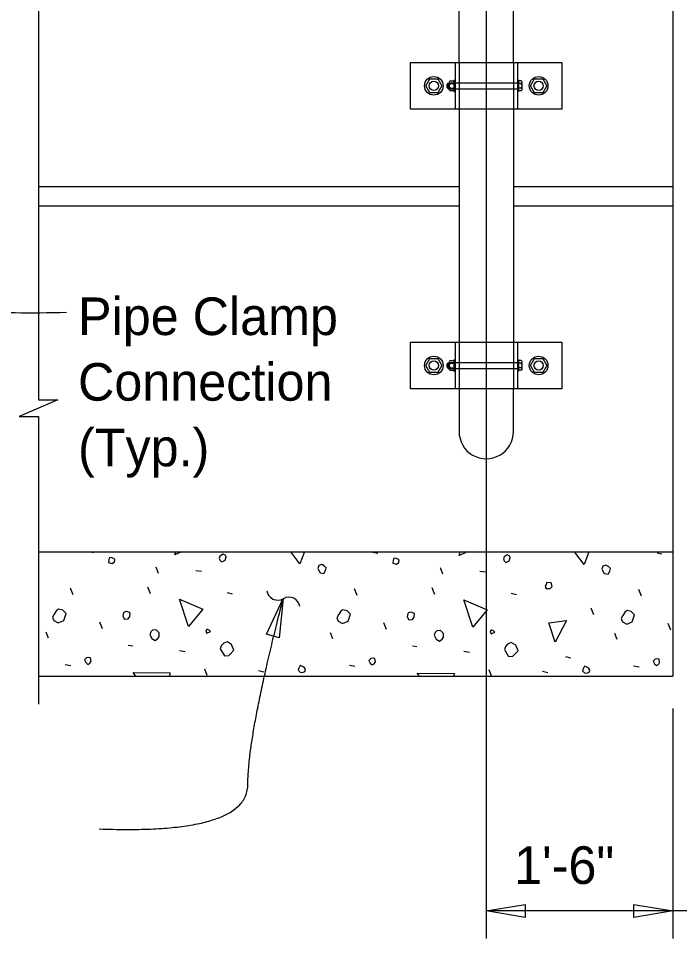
# Model space of a CAD drawing. Extents: x 0 to 41.2, y 0 to 26.
# Drawn here: x 23.735 to 27.279, y 12.395 to 17.331 of the extents above; entities that cross this region are included whole.
import ezdxf

# ---------------------------------------------------------------- set-up
doc = ezdxf.new("R2010")
doc.units = 0
for name, color, linetype in [('CL_Major', 7, 'Continuous'), ('Dimension', 7, 'Continuous'), ('Miscellaneous', 7, 'Continuous'), ('SteelMisc', 7, 'Continuous'), ('SteelMisc_h', 7, 'Continuous'), ('SupstrConc', 7, 'Continuous'), ('TextStructures', 7, 'Continuous')]:
    doc.layers.add(name, color=color, linetype=linetype)

msp = doc.modelspace()

# ---------------------------------------------------------------- linework, layer by layer
at = {"layer": 'CL_Major'}
msp.add_line((26.2429, 25.6784), (26.2429, 12.3953), dxfattribs=at)
at = {"layer": 'Dimension'}
for p, q in [((27.2429, 13.6294), (27.2429, 12.3953)), ((28.5763, 12.5434), (26.2429, 12.5434))]:
    msp.add_line(p, q, dxfattribs=at)
for points in [[(23.8431, 20.1983), (23.8431, 19.1806), (23.9465, 19.1806), (23.8431, 19.1356), (23.7398, 19.0906), (23.8431, 19.0906), (23.8431, 17.1361)], [(23.8431, 17.1361), (23.8431, 15.2855), (23.9464, 15.2855), (23.8431, 15.2405), (23.7397, 15.1955), (23.8431, 15.1955), (23.8431, 13.653)]]:
    msp.add_lwpolyline(points, dxfattribs=at)
for points in [[(25.1546, 14.219), (25.1324, 14.009), (25.0644, 14.0281)], [(26.2429, 12.5434), (26.4512, 12.5787), (26.4512, 12.5081)], [(27.2429, 12.5434), (27.0347, 12.5081), (27.0347, 12.5787)]]:
    msp.add_lwpolyline(points, close=True, dxfattribs=at)
for centre, start, end in [((25.1255, 14.2702), 188.4294, 300.1567), ((25.1854, 14.1671), 8.4294, 120.1567)]:
    msp.add_arc(centre, 0.0596, start, end, dxfattribs=at)
for points in [[(23.9932, 15.7529), (23.0399, 15.7236), (23.3618, 16.2556), (23.3935, 16.8155), (23.1813, 16.9916), (22.6122, 16.9694)], [(24.1685, 12.9835), (24.964, 12.9538), (24.9656, 13.4901), (25.1547, 14.2189)]]:
    msp.add_open_spline(points, degree=2, dxfattribs=at)
at = {"layer": 'Miscellaneous'}
for p, q in [((26.0354, 16.9625), (26.0354, 16.9746)), ((26.0411, 16.9625), (26.0411, 16.9746)), ((26.0354, 15.4625), (26.0354, 15.4746)), ((26.0411, 15.4625), (26.0411, 15.4746)), ((24.1186, 14.4695), (24.1373, 14.4657)), ((25.6346, 14.4675), (25.6611, 14.4622)), ((27.1584, 14.4639), (27.185, 14.4586)), ((24.4856, 14.3543), (24.4732, 14.3879)), ((24.6853, 14.3702), (24.7172, 14.3667)), ((26.0094, 14.3508), (25.997, 14.3844)), ((26.2092, 14.3667), (26.241, 14.3632)), ((24.0277, 14.2394), (24.0136, 14.2748)), ((24.4432, 14.2447), (24.429, 14.2801)), ((25.5515, 14.2359), (25.5374, 14.2712)), ((25.967, 14.2412), (25.9528, 14.2765)), ((27.0754, 14.2324), (27.0612, 14.2677)), ((24.8533, 14.2518), (24.8816, 14.2447)), ((26.3771, 14.2483), (26.4054, 14.2412)), ((26.819, 14.1316), (26.8049, 14.1669)), ((24.1851, 14.0573), (24.1709, 14.0927)), ((25.7089, 14.0538), (25.6947, 14.0892)), ((27.2327, 14.0503), (27.2185, 14.0856)), ((23.8969, 14.0061), (23.8845, 14.0397)), ((25.4207, 14.0025), (25.4084, 14.0361)), ((26.9445, 13.999), (26.9322, 14.0326)), ((24.3229, 13.969), (24.3477, 13.9654)), ((24.5987, 13.9407), (24.6288, 13.9354)), ((25.8468, 13.9654), (25.8715, 13.9619)), ((26.1225, 13.9371), (26.1526, 13.9318)), ((26.667, 13.9089), (26.6953, 13.9018)), ((23.9853, 13.8647), (24.0154, 13.8594)), ((24.7472, 13.8063), (24.7348, 13.8399)), ((25.0212, 13.8328), (25.0495, 13.8258)), ((25.5091, 13.8611), (25.5392, 13.8558)), ((26.271, 13.8028), (26.2587, 13.8364)), ((26.545, 13.8293), (26.5733, 13.8222)), ((27.0329, 13.8576), (27.063, 13.8523))]:
    msp.add_line(p, q, dxfattribs=at)
for points in [[(24.574, 14.4533), (24.5789, 14.4695)], [(24.6099, 14.4695), (24.574, 14.4533)], [(25.244, 14.4056), (25.1954, 14.4695)], [(25.2678, 14.4695), (25.244, 14.4056)], [(26.0978, 14.4498), (26.1038, 14.4695)], [(26.1416, 14.4695), (26.0978, 14.4498)], [(26.7678, 14.4021), (26.7165, 14.4695)], [(26.793, 14.4695), (26.7678, 14.4021)], [(24.2186, 14.4127), (24.2381, 14.4074), (24.2505, 14.4162), (24.2522, 14.4286), (24.2487, 14.4321), (24.2346, 14.4392), (24.2222, 14.4374), (24.2204, 14.425), (24.2186, 14.4127)], [(24.8215, 14.418), (24.8285, 14.418), (24.8427, 14.425), (24.848, 14.4409), (24.8462, 14.4498), (24.8321, 14.4569), (24.8144, 14.4463), (24.8109, 14.4356), (24.8144, 14.425), (24.8215, 14.418)], [(25.7425, 14.4091), (25.7619, 14.4038), (25.7743, 14.4127), (25.7761, 14.425), (25.7725, 14.4286), (25.7584, 14.4356), (25.746, 14.4339), (25.7442, 14.4215), (25.7425, 14.4091)], [(26.3453, 14.4144), (26.3523, 14.4144), (26.3665, 14.4215), (26.3718, 14.4374), (26.37, 14.4463), (26.3559, 14.4533), (26.3382, 14.4427), (26.3347, 14.4321), (26.3382, 14.4215), (26.3453, 14.4144)], [(25.3429, 14.3738), (25.3518, 14.3579), (25.373, 14.3543), (25.3818, 14.3702), (25.3854, 14.3844), (25.3765, 14.3932), (25.3606, 14.4021), (25.3447, 14.3968), (25.3394, 14.3808), (25.3429, 14.3738)], [(26.8668, 14.3702), (26.8756, 14.3543), (26.8968, 14.3508), (26.9057, 14.3667), (26.9092, 14.3808), (26.9004, 14.3897), (26.8844, 14.3985), (26.8685, 14.3932), (26.8632, 14.3773), (26.8668, 14.3702)], [(26.5645, 14.273), (26.5857, 14.273), (26.5963, 14.2836), (26.591, 14.3031), (26.568, 14.3048), (26.5645, 14.2942), (26.5592, 14.2854), (26.5645, 14.273), (26.5609, 14.2765)], [(24.6464, 14.0697), (24.5987, 14.2164), (24.7242, 14.1616), (24.6464, 14.0697)], [(26.1703, 14.0662), (26.1225, 14.2129), (26.248, 14.1581), (26.1703, 14.0662)], [(23.9252, 14.1015), (23.9482, 14.0892), (23.9782, 14.1015), (23.9906, 14.1387), (23.9729, 14.1563), (23.9499, 14.1616), (23.9393, 14.1546), (23.927, 14.1351), (23.9181, 14.1192), (23.9252, 14.1015)], [(24.2947, 14.1245), (24.3035, 14.1086), (24.3229, 14.1104), (24.3318, 14.1228), (24.3336, 14.1422), (24.3212, 14.1475), (24.3123, 14.1493), (24.3017, 14.1457), (24.2982, 14.1422), (24.2947, 14.1245)], [(25.449, 14.098), (25.472, 14.0856), (25.502, 14.098), (25.5144, 14.1351), (25.4967, 14.1528), (25.4738, 14.1581), (25.4632, 14.151), (25.4508, 14.1316), (25.4419, 14.1157), (25.449, 14.098)], [(25.8185, 14.121), (25.8273, 14.1051), (25.8468, 14.1068), (25.8556, 14.1192), (25.8574, 14.1387), (25.845, 14.144), (25.8362, 14.1457), (25.8255, 14.1422), (25.822, 14.1387), (25.8185, 14.121)], [(26.9728, 14.0945), (26.9958, 14.0821), (27.0259, 14.0945), (27.0382, 14.1316), (27.0206, 14.1493), (26.9976, 14.1546), (26.987, 14.1475), (26.9746, 14.1281), (26.9658, 14.1121), (26.9728, 14.0945)], [(26.6122, 13.9849), (26.5786, 14.0892), (26.6723, 14.1015), (26.6122, 13.9849)], [(24.4396, 14.0255), (24.4502, 14.0043), (24.4679, 13.9937), (24.482, 14.0043), (24.4891, 14.0149), (24.4891, 14.0361), (24.4732, 14.052), (24.4538, 14.0503), (24.4449, 14.0414), (24.4396, 14.0255)], [(24.7454, 14.0344), (24.7649, 14.0432), (24.7578, 14.0503), (24.7454, 14.0556), (24.7401, 14.0432), (24.7454, 14.0344)], [(25.9634, 14.022), (25.974, 14.0008), (25.9917, 13.9902), (26.0059, 14.0008), (26.0129, 14.0114), (26.0129, 14.0326), (25.997, 14.0485), (25.9776, 14.0467), (25.9687, 14.0379), (25.9634, 14.022)], [(26.2693, 14.0308), (26.2887, 14.0397), (26.2816, 14.0467), (26.2693, 14.052), (26.264, 14.0397), (26.2693, 14.0308)], [(24.8162, 13.9495), (24.8391, 13.9124), (24.8621, 13.9142), (24.871, 13.923), (24.8904, 13.9424), (24.878, 13.9725), (24.8533, 13.9866), (24.8356, 13.9796), (24.8215, 13.9654), (24.8162, 13.9495)], [(26.34, 13.946), (26.3629, 13.9089), (26.3859, 13.9106), (26.3948, 13.9195), (26.4142, 13.9389), (26.4018, 13.969), (26.3771, 13.9831), (26.3594, 13.976), (26.3453, 13.9619), (26.34, 13.946)], [(24.0967, 13.877), (24.1073, 13.8664), (24.1179, 13.8735), (24.125, 13.8841), (24.1214, 13.9018), (24.1126, 13.9035), (24.1002, 13.9018), (24.0896, 13.8912), (24.0967, 13.877)], [(25.6205, 13.8735), (25.6311, 13.8629), (25.6417, 13.87), (25.6488, 13.8806), (25.6452, 13.8982), (25.6364, 13.9), (25.624, 13.8982), (25.6134, 13.8876), (25.6205, 13.8735)], [(27.1443, 13.87), (27.1549, 13.8594), (27.1655, 13.8664), (27.1726, 13.877), (27.1691, 13.8947), (27.1602, 13.8965), (27.1478, 13.8947), (27.1372, 13.8841), (27.1443, 13.87)], [(24.3642, 13.8028), (24.3495, 13.8222), (24.5492, 13.8205), (24.5426, 13.8028)], [(25.2457, 13.824), (25.2581, 13.8222), (25.2705, 13.8275), (25.274, 13.8381), (25.2687, 13.847), (25.2581, 13.8541), (25.2457, 13.8594), (25.2386, 13.8452), (25.2351, 13.8346), (25.2457, 13.824)], [(26.7695, 13.8205), (26.7819, 13.8187), (26.7943, 13.824), (26.7978, 13.8346), (26.7925, 13.8434), (26.7819, 13.8505), (26.7695, 13.8558), (26.7625, 13.8417), (26.7589, 13.8311), (26.7695, 13.8205)], [(25.8854, 13.8028), (25.8733, 13.8187), (26.073, 13.8169), (26.0678, 13.8028)]]:
    msp.add_lwpolyline(points, dxfattribs=at)
at = {"layer": 'SteelMisc'}
for p, q in [((26.0971, 17.0944), (26.0971, 17.6079)), ((26.3888, 17.0944), (26.3888, 17.6079)), ((25.837, 17.0944), (26.6489, 17.0944)), ((25.837, 16.8444), (25.837, 17.0944)), ((26.0763, 17.0944), (26.0763, 16.8444)), ((26.4096, 17.0944), (26.4096, 16.8444)), ((26.6489, 17.0944), (26.6489, 16.8444)), ((26.0326, 16.9774), (26.0382, 16.984)), ((26.0382, 16.984), (26.0447, 16.984)), ((26.0382, 16.9541), (26.0382, 16.984)), ((26.0447, 16.9873), (26.0447, 16.9516)), ((26.0494, 16.9824), (26.0697, 16.9824)), ((26.0496, 16.9954), (26.0697, 16.9954)), ((26.0697, 16.9997), (26.0697, 16.9391)), ((26.0697, 16.9997), (26.0763, 16.9997)), ((26.0697, 16.9954), (26.0697, 16.9435)), ((26.4159, 16.9997), (26.4098, 16.9997)), ((26.4159, 16.9997), (26.4159, 16.9391)), ((26.4306, 16.9954), (26.4159, 16.9954)), ((26.4307, 16.9824), (26.4159, 16.9824)), ((26.4357, 16.95), (26.4357, 16.9889)), ((26.0326, 16.9597), (26.0326, 16.9774)), ((26.0326, 16.9597), (26.0382, 16.9541)), ((26.0382, 16.9541), (26.0447, 16.9541)), ((26.0494, 16.9565), (26.0697, 16.9565)), ((26.0497, 16.9435), (26.0697, 16.9435)), ((26.0697, 16.9391), (26.0763, 16.9391)), ((26.4159, 16.9391), (26.4098, 16.9391)), ((26.4307, 16.9564), (26.4159, 16.9564)), ((26.4306, 16.9434), (26.4159, 16.9434)), ((26.6489, 16.8444), (25.837, 16.8444)), ((26.0971, 16.8444), (26.0971, 15.5944)), ((26.3888, 16.8444), (26.3888, 15.5944)), ((25.837, 15.5944), (26.6489, 15.5944)), ((25.837, 15.3444), (25.837, 15.5944)), ((26.0763, 15.5944), (26.0763, 15.3444)), ((26.4096, 15.5944), (26.4096, 15.3444)), ((26.6489, 15.5944), (26.6489, 15.3444)), ((26.0697, 15.4997), (26.0697, 15.4391)), ((26.0697, 15.4997), (26.0763, 15.4997)), ((26.4159, 15.4997), (26.4098, 15.4997)), ((26.4159, 15.4997), (26.4159, 15.4391)), ((26.0326, 15.4774), (26.0382, 15.484)), ((26.0326, 15.4597), (26.0326, 15.4774)), ((26.0326, 15.4597), (26.0382, 15.4541)), ((26.0382, 15.484), (26.0447, 15.484)), ((26.0382, 15.4541), (26.0382, 15.484)), ((26.0382, 15.4541), (26.0447, 15.4541)), ((26.0447, 15.4873), (26.0447, 15.4516)), ((26.0494, 15.4824), (26.0697, 15.4824)), ((26.0494, 15.4565), (26.0697, 15.4565)), ((26.0496, 15.4954), (26.0697, 15.4954)), ((26.0697, 15.4954), (26.0697, 15.4435)), ((26.4306, 15.4954), (26.4159, 15.4954)), ((26.4307, 15.4824), (26.4159, 15.4824)), ((26.4307, 15.4564), (26.4159, 15.4564)), ((26.4357, 15.45), (26.4357, 15.4889)), ((26.0497, 15.4435), (26.0697, 15.4435)), ((26.0697, 15.4391), (26.0763, 15.4391)), ((26.4159, 15.4391), (26.4098, 15.4391)), ((26.4306, 15.4434), (26.4159, 15.4434)), ((26.6489, 15.3444), (25.837, 15.3444)), ((26.097, 15.3444), (26.097, 15.1153)), ((26.3887, 15.1153), (26.3887, 15.3444))]:
    msp.add_line(p, q, dxfattribs=at)
for points in [[(25.9403, 17.007), (25.9836, 17.007), (26.0053, 16.9694), (25.9836, 16.9319), (25.9403, 16.9319), (25.9186, 16.9694)], [(26.5023, 17.007), (26.5456, 17.007), (26.5673, 16.9694), (26.5456, 16.9319), (26.5023, 16.9319), (26.4806, 16.9694)], [(25.9403, 15.507), (25.9836, 15.507), (26.0053, 15.4694), (25.9836, 15.4319), (25.9403, 15.4319), (25.9186, 15.4694)], [(26.5023, 15.507), (26.5456, 15.507), (26.5673, 15.4694), (26.5456, 15.4319), (26.5023, 15.4319), (26.4806, 15.4694)]]:
    msp.add_lwpolyline(points, close=True, dxfattribs=at)
for centre, radius in [((25.962, 16.9694), 0.05), ((25.962, 16.9694), 0.025), ((26.5239, 16.9694), 0.05), ((26.5239, 16.9694), 0.025), ((25.962, 15.4694), 0.05), ((26.5239, 15.4694), 0.05), ((25.962, 15.4694), 0.025), ((26.5239, 15.4694), 0.025)]:
    msp.add_circle(centre, radius, dxfattribs=at)
for centre, radius, start, end in [((26.0513, 16.9889), 0.00674, 104.4891, 254.1889), ((26.0642, 16.9694), 0.0196, 138.628, 221.372), ((26.4289, 16.9889), 0.00673, 285.7823, 75.5404), ((26.416, 16.9694), 0.0196, 318.628, 41.372), ((26.0513, 16.95), 0.00673, 105.7823, 255.5404), ((26.4289, 16.95), 0.00674, 284.4891, 74.1889), ((26.0513, 15.4889), 0.00674, 104.4891, 254.1889), ((26.0642, 15.4694), 0.0196, 138.628, 221.372), ((26.0513, 15.45), 0.00673, 105.7823, 255.5404), ((26.4289, 15.4889), 0.00673, 285.7823, 75.5404), ((26.4289, 15.45), 0.00674, 284.4891, 74.1889), ((26.416, 15.4694), 0.0196, 318.628, 41.372)]:
    msp.add_arc(centre, radius, start, end, dxfattribs=at)
msp.add_ellipse((26.2429, 15.1153), major_axis=(0, 0.1458), ratio=0.999499, start_param=1.570796, end_param=4.712389, dxfattribs=at)
at = {"layer": 'SteelMisc_h'}
for p, q in [((26.0971, 17.0944), (26.0971, 16.8444)), ((26.3888, 17.0944), (26.3888, 16.8444)), ((26.4096, 16.984), (26.0447, 16.984)), ((26.0447, 16.9541), (26.4096, 16.9541)), ((26.0971, 15.5944), (26.0971, 15.3444)), ((26.3888, 15.5944), (26.3888, 15.3444)), ((26.4096, 15.484), (26.0447, 15.484)), ((26.0447, 15.4541), (26.4096, 15.4541))]:
    msp.add_line(p, q, dxfattribs=at)
at = {"layer": 'SupstrConc'}
for p, q in [((27.2429, 17.4693), (27.2429, 13.8028)), ((23.8431, 16.4295), (26.0971, 16.4295)), ((26.3888, 16.4295), (27.2428, 16.4295)), ((23.8431, 16.3254), (26.0971, 16.3254)), ((26.3888, 16.3254), (27.2428, 16.3254)), ((23.8431, 14.4695), (27.2429, 14.4695)), ((23.8431, 13.8028), (27.2429, 13.8028))]:
    msp.add_line(p, q, dxfattribs=at)

# ---------------------------------------------------------------- texts
at = {"layer": 'Dimension'}
for s, p in [('Pipe Clamp ', (24.0545, 15.6326)), ('Connection ', (24.0545, 15.2806)), ('(Typ.)', (24.0545, 14.9286))]:
    msp.add_text(s, height=0.2016, dxfattribs=at).set_placement(p)
at = {"layer": 'TextStructures'}
msp.add_text('1\'-6"', height=0.2016, dxfattribs=at).set_placement((26.3923, 12.6886))

doc.saveas('drawing.dxf')
